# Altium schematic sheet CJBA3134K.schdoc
size 127 x 101 mm
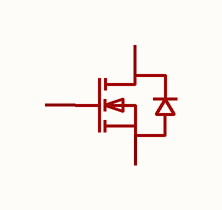
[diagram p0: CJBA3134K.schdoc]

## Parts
Q?  cjba3134k  [DFN1006-3L_L1.0-W0.6-BL]  (value not drawn)

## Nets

Not connected (* = marked no-connect by the designer): Q? 1(S) 2(D) 3(G)

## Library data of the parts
Q? = cjba3134k: 数量:1个N沟道;漏源电压(Vdss):20V;连续漏极电流(Id):750mA;导通电阻(RDS(on)):500mΩ@4.5V;耗散功率(Pd):100mW;阈值电压(Vgs(th)):1.1V;; Manufacturer: CJ(江苏长电/长晶); AddInBom: yes; ModelId: 89988d492fd24034894d084d947c97a1; ModelName: DFN1006-3L_L1.0-W0.6-H0.4-BL; ModelTransform: 39.764,24.0157,0,0,0,0,0,0,0; Number: 1个N沟道; Drain to Source Voltage: 20V; Current - Continuous Drain(Id): 750mA; Pd - Power Dissipation: 100mW; Gate Threshold Voltage (Vgs(th)): 1.1V; Input Capacitance(Ciss): 120pF; Reverse Transfer Capacitance (Crss@Vds): 15pF; Type: N沟道; Output Capacitance(Coss): 13pF; Vgs: ±12V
